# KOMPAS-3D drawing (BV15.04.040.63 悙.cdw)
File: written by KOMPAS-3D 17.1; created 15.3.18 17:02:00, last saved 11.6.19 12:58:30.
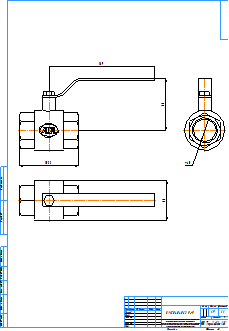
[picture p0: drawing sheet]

Sheet 1: A2, portrait

Title block, sheet 1: name: BV15.04.040.63 Р/Р; material: Внимание! Данный продукт является объектом авторского права ООО «Торговый Дом АДЛ». / Запрещается изменение, копирование, распространение / (в том числе путем копирования на другие сайты и ресурсы в Интернете) / или любое иное использование информации и объектов без предварительного / согласия правообладателя (ООО «Торговый Дом АДЛ»).; mass: 1,9; sheets: 1; organisation: ООО "Торговый дом АДЛ"; sheet format: A2; stored path: \\adlc.lan\data\АДЛ_ПКД\3D-модели\ADL production\Краны шаровые серии BV\BV15\KOMPAS 2D\BV15.04.040.63 РР.cdw

Views: Вид 1, Проекционный вид 2, Проекционный вид 3
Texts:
  kka
  adl
Dimensions and other numbers on the sheet: 105,5; 189; 93; 40; 72; 1:1; 1; 1,9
